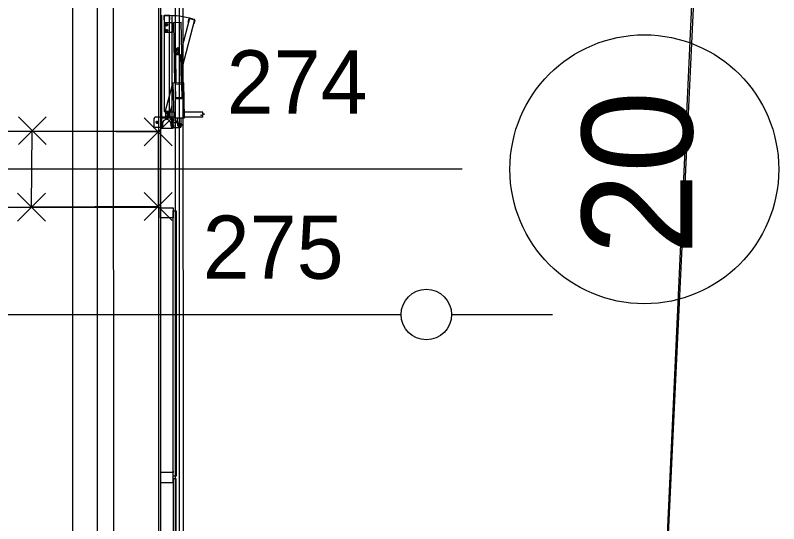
# Model space of a CAD drawing. Extents: x -264205 to -263659, y -1242401 to -1242060.
# Drawn here: x -263796.19 to -263790.15, y -1242212.69 to -1242208.66 of the extents above; entities that cross this region are included whole.
import ezdxf

# ---------------------------------------------------------------- set-up
doc = ezdxf.new("R2010")
doc.units = 0
for name, color, linetype in [('BOD_CISLO', 7, 'Continuous'), ('BOD_SYMBOL', 7, 'Continuous'), ('KFA_SO_10-1_BETONOVE_STLPY', 7, 'Continuous'), ('KFA_SO_10-1_PLACHTY', 7, 'Continuous'), ('KFA_SO_10-1_STRECHY', 7, 'Continuous'), ('KFA_SO_10-1_TRIBUNA_C_OBVOD', 7, 'Continuous'), ('OBRUBNIKY_KOMUNIKACIE_PROJEKT', 7, 'Continuous'), ('OSI_STAVBY_KFA', 7, 'Continuous'), ('SITUACIA_DSP_2D', 7, 'Continuous')]:
    doc.layers.add(name, color=color, linetype=linetype)

msp = doc.modelspace()

# ---------------------------------------------------------------- linework, layer by layer
at = {"layer": 'BOD_SYMBOL'}
for p, q in [((-263796.1675, -1242209.6875), (-263795.9465, -1242209.4665)), ((-263795.9465, -1242209.6875), (-263796.1675, -1242209.4665)), ((-263795.1705, -1242209.6965), (-263794.9495, -1242209.4755)), ((-263794.9495, -1242209.6965), (-263795.1705, -1242209.4755)), ((-263796.1735, -1242210.2935), (-263795.9525, -1242210.0725)), ((-263795.9525, -1242210.2935), (-263796.1735, -1242210.0725)), ((-263795.1715, -1242210.2885), (-263794.9505, -1242210.0675)), ((-263794.9505, -1242210.2885), (-263795.1715, -1242210.0675))]:
    msp.add_line(p, q, dxfattribs=at)
at = {"layer": 'KFA_SO_10-1_BETONOVE_STLPY'}
msp.add_lwpolyline([(-263795.06, -1242209.586), (-263795.061, -1242210.178), (-263796.063, -1242210.183), (-263796.057, -1242209.577)], close=True, dxfattribs=at)
at = {"layer": 'KFA_SO_10-1_PLACHTY'}
for p, q in [((-263794.856, -1242227.181), (-263794.865, -1242196.184)), ((-263790.262, -1242196.192), (-263791.751, -1242228.358))]:
    msp.add_line(p, q, dxfattribs=at)
for points in [[(-263795.396, -1242226.823), (-263795.427, -1242195.892), (-263795.456, -1242167.905), (-263795.427, -1242160.909), (-263795.402, -1242132.887), (-263795.428, -1242101.98)], [(-263794.927, -1242226.983), (-263794.921, -1242199.7), (-263794.865, -1242196.184)], [(-263791.76, -1242228.35), (-263790.229, -1242196.189)]]:
    msp.add_lwpolyline(points, dxfattribs=at)
at = {"layer": 'KFA_SO_10-1_STRECHY'}
msp.add_line((-263795.734, -1242227.196), (-263795.754, -1242101.588), dxfattribs=at)
at = {"layer": 'KFA_SO_10-1_TRIBUNA_C_OBVOD'}
msp.add_lwpolyline([(-263795.284, -1242101.267), (-263795.051, -1242101.819), (-263795.059, -1242226.991), (-263795.286, -1242227.548)], dxfattribs=at)
at = {"layer": 'OBRUBNIKY_KOMUNIKACIE_PROJEKT'}
msp.add_line((-263794.8928, -1242101.3822), (-263794.8928, -1242227.3822), dxfattribs=at)
at = {"layer": 'OSI_STAVBY_KFA'}
for p, q in [((-263795.5428, -1242083.2372), (-263795.5428, -1242246.7072)), ((-263792.6528, -1242209.8822), (-263909.3428, -1242209.8822)), ((-263792.6528, -1242209.8822), (-263792.6528, -1242209.8822))]:
    msp.add_line(p, q, dxfattribs=at)
msp.add_circle((-263791.2101, -1242209.8825), 1.0643, dxfattribs=at)
at = {"layer": 'SITUACIA_DSP_2D'}
for p, q in [((-263794.8928, -1242101.3822), (-263794.8928, -1242227.3822)), ((-263795.0428, -1242101.7691), (-263795.0428, -1242226.9954)), ((-263795.0327, -1242208.6624), (-263795.0327, -1242209.5569)), ((-263795.0147, -1242208.6694), (-263795.0147, -1242208.6994)), ((-263795.0127, -1242208.6674), (-263795.0127, -1242209.4259)), ((-263794.9727, -1242208.6674), (-263795.0127, -1242208.6674)), ((-263794.9747, -1242208.6654), (-263795.0107, -1242208.6654)), ((-263794.9757, -1242208.6692), (-263794.9667, -1242208.6692)), ((-263794.9727, -1242208.6674), (-263794.9727, -1242209.4259)), ((-263794.9707, -1242208.6694), (-263794.9707, -1242208.6994)), ((-263794.9527, -1242208.6624), (-263794.9527, -1242209.5569)), ((-263795.0127, -1242208.6994), (-263795.0147, -1242208.6994)), ((-263795.0067, -1242208.7249), (-263795.0067, -1242208.7999)), ((-263794.9527, -1242208.7249), (-263795.0067, -1242208.7249)), ((-263794.9927, -1242208.732), (-263794.9995, -1242208.736)), ((-263794.9859, -1242208.736), (-263794.9927, -1242208.732)), ((-263794.9698, -1242208.6845), (-263794.9727, -1242208.6845)), ((-263794.9707, -1242208.6994), (-263794.9727, -1242208.6994)), ((-263794.9467, -1242208.7249), (-263794.9527, -1242208.7249)), ((-263794.9467, -1242208.7249), (-263794.9467, -1242208.7999)), ((-263794.9394, -1242208.7202), (-263794.8784, -1242208.7189)), ((-263794.9394, -1242208.7202), (-263794.9298, -1242209.2011)), ((-263794.8688, -1242209.1999), (-263794.8784, -1242208.7189)), ((-263794.8111, -1242208.6885), (-263794.8742, -1242208.9316)), ((-263794.7725, -1242208.6989), (-263794.8713, -1242209.0755)), ((-263794.8213, -1242208.7189), (-263794.8136, -1242208.6899)), ((-263794.8194, -1242208.7194), (-263794.8213, -1242208.7189)), ((-263794.8111, -1242208.6885), (-263794.7725, -1242208.6989)), ((-263794.8087, -1242208.6871), (-263794.7739, -1242208.6964)), ((-263794.7788, -1242208.7303), (-263794.7807, -1242208.7298)), ((-263794.771, -1242208.7013), (-263794.7788, -1242208.7303)), ((-263794.9995, -1242208.736), (-263794.9995, -1242208.7438)), ((-263794.9995, -1242208.7438), (-263794.9927, -1242208.7478)), ((-263794.9927, -1242208.777), (-263794.9995, -1242208.781)), ((-263794.9995, -1242208.781), (-263794.9995, -1242208.7888)), ((-263794.9995, -1242208.7888), (-263794.9927, -1242208.7928)), ((-263794.9927, -1242208.7478), (-263794.9859, -1242208.7438)), ((-263794.9859, -1242208.781), (-263794.9927, -1242208.777)), ((-263794.9927, -1242208.7928), (-263794.9859, -1242208.7888)), ((-263794.9859, -1242208.7438), (-263794.9859, -1242208.736)), ((-263794.9859, -1242208.7888), (-263794.9859, -1242208.781)), ((-263794.9527, -1242208.7999), (-263795.0067, -1242208.7999)), ((-263794.9467, -1242208.7999), (-263794.9527, -1242208.7999)), ((-263794.9092, -1242208.9566), (-263794.9167, -1242208.9435)), ((-263794.8939, -1242208.9725), (-263794.9139, -1242208.9729)), ((-263794.9139, -1242208.9729), (-263794.9138, -1242208.9779)), ((-263794.9125, -1242208.9648), (-263794.9138, -1242208.9656)), ((-263794.9138, -1242208.9656), (-263794.9137, -1242208.9721)), ((-263794.9124, -1242208.9728), (-263794.9137, -1242208.9721)), ((-263794.8955, -1242208.9645), (-263794.9125, -1242208.9648)), ((-263794.8954, -1242208.9725), (-263794.9124, -1242208.9728)), ((-263794.9092, -1242208.9566), (-263794.8992, -1242208.9564)), ((-263794.9092, -1242208.9566), (-263794.909, -1242208.9648)), ((-263794.9089, -1242208.9655), (-263794.9088, -1242208.972)), ((-263794.8992, -1242208.9564), (-263794.8922, -1242208.943)), ((-263794.8992, -1242208.9564), (-263794.899, -1242208.9646)), ((-263794.8991, -1242208.9653), (-263794.899, -1242208.9718)), ((-263794.8955, -1242208.9645), (-263794.8942, -1242208.9652)), ((-263794.8954, -1242208.9725), (-263794.8941, -1242208.9717)), ((-263794.8942, -1242208.9652), (-263794.8941, -1242208.9717)), ((-263794.8939, -1242208.9725), (-263794.8938, -1242208.9775)), ((-263794.8838, -1242208.9773), (-263794.9238, -1242208.9781)), ((-263794.9238, -1242208.9781), (-263794.9193, -1242209.2009)), ((-263794.8838, -1242208.9773), (-263794.8793, -1242209.2001)), ((-263794.8558, -1242209.1996), (-263794.9428, -1242209.2013)), ((-263794.9428, -1242209.2013), (-263794.9373, -1242209.4763)), ((-263794.9243, -1242209.201), (-263794.9218, -1242209.327)), ((-263794.8741, -1242209.21), (-263794.9241, -1242209.211)), ((-263794.8743, -1242209.2), (-263794.8718, -1242209.326)), ((-263794.8504, -1242209.4745), (-263794.8558, -1242209.1996)), ((-263794.9527, -1242209.2248), (-263795.0055, -1242209.4216)), ((-263794.872, -1242209.316), (-263794.922, -1242209.317)), ((-263794.8718, -1242209.326), (-263794.9218, -1242209.327)), ((-263794.9527, -1242209.3794), (-263794.9668, -1242209.4319)), ((-263794.9727, -1242209.4259), (-263795.0127, -1242209.4259)), ((-263795.0055, -1242209.4216), (-263794.9668, -1242209.4319)), ((-263795.0052, -1242209.4259), (-263795.0052, -1242209.4359)), ((-263795.0052, -1242209.4259), (-263794.9802, -1242209.4259)), ((-263795.0052, -1242209.4359), (-263794.9802, -1242209.4359)), ((-263794.9982, -1242209.4235), (-263795.0008, -1242209.4332)), ((-263794.9767, -1242209.4397), (-263795.0008, -1242209.4332)), ((-263795.0008, -1242209.4455), (-263794.9937, -1242209.4359)), ((-263794.9937, -1242209.4669), (-263795.0008, -1242209.4573)), ((-263794.9897, -1242209.4362), (-263794.999, -1242209.4436)), ((-263794.9937, -1242209.4359), (-263794.9917, -1242209.4359)), ((-263794.9917, -1242209.4359), (-263794.9847, -1242209.4455)), ((-263794.9847, -1242209.4573), (-263794.9917, -1242209.4669)), ((-263794.9878, -1242209.4367), (-263794.9897, -1242209.4362)), ((-263794.9834, -1242209.4478), (-263794.9878, -1242209.4367)), ((-263794.9772, -1242209.4504), (-263794.9868, -1242209.4433)), ((-263794.9868, -1242209.4594), (-263794.9772, -1242209.4524)), ((-263794.9802, -1242209.4259), (-263794.9802, -1242209.4359)), ((-263794.9772, -1242209.4639), (-263794.9772, -1242209.4389)), ((-263794.9672, -1242209.4389), (-263794.9772, -1242209.4389)), ((-263794.9772, -1242209.4524), (-263794.9772, -1242209.4504)), ((-263794.9741, -1242209.43), (-263794.9767, -1242209.4397)), ((-263794.9672, -1242209.4314), (-263794.9672, -1242209.4714)), ((-263794.9382, -1242209.4314), (-263794.9672, -1242209.4314)), ((-263794.9672, -1242209.4639), (-263794.9672, -1242209.4389)), ((-263794.7071, -1242209.4314), (-263794.8512, -1242209.4314)), ((-263794.7221, -1242209.4554), (-263794.6921, -1242209.4474)), ((-263794.7071, -1242209.4594), (-263794.7221, -1242209.4554)), ((-263794.7071, -1242209.4434), (-263794.7071, -1242209.4314)), ((-263794.6921, -1242209.4474), (-263794.7071, -1242209.4434)), ((-263795.0927, -1242209.5569), (-263795.0927, -1242209.4809)), ((-263795.0327, -1242209.4709), (-263795.0827, -1242209.4709)), ((-263795.0547, -1242209.5109), (-263795.0807, -1242209.5109)), ((-263795.0677, -1242209.5239), (-263795.0677, -1242209.4979)), ((-263794.9527, -1242209.4709), (-263795.0327, -1242209.4709)), ((-263794.9527, -1242209.4769), (-263795.0327, -1242209.4769)), ((-263795.0052, -1242209.4669), (-263794.9802, -1242209.4669)), ((-263795.0052, -1242209.4769), (-263795.0052, -1242209.4669)), ((-263795.0052, -1242209.4769), (-263794.9802, -1242209.4769)), ((-263794.9917, -1242209.4669), (-263794.9937, -1242209.4669)), ((-263794.9802, -1242209.4769), (-263794.9802, -1242209.4669)), ((-263794.9672, -1242209.4639), (-263794.9772, -1242209.4639)), ((-263794.9374, -1242209.4714), (-263794.9672, -1242209.4714)), ((-263794.9375, -1242209.4709), (-263794.9527, -1242209.4709)), ((-263794.9527, -1242209.4819), (-263794.9427, -1242209.4819)), ((-263794.9527, -1242209.5519), (-263794.9527, -1242209.4819)), ((-263794.9329, -1242209.4924), (-263794.9472, -1242209.4924)), ((-263794.9427, -1242209.5519), (-263794.9427, -1242209.4819)), ((-263794.9427, -1242209.484), (-263794.9427, -1242209.5008)), ((-263794.941, -1242209.484), (-263794.9427, -1242209.484)), ((-263794.941, -1242209.5008), (-263794.9427, -1242209.5008)), ((-263794.9427, -1242209.5114), (-263794.9081, -1242209.5114)), ((-263794.941, -1242209.484), (-263794.941, -1242209.5008)), ((-263794.941, -1242209.4856), (-263794.941, -1242209.4992)), ((-263794.9355, -1242209.4856), (-263794.941, -1242209.4856)), ((-263794.941, -1242209.4924), (-263794.9364, -1242209.4924)), ((-263794.941, -1242209.4992), (-263794.9355, -1242209.4992)), ((-263794.9373, -1242209.4763), (-263794.8504, -1242209.4745)), ((-263794.9355, -1242209.4992), (-263794.9355, -1242209.4856)), ((-263794.9082, -1242209.5109), (-263794.9273, -1242209.5109)), ((-263794.9177, -1242209.5114), (-263794.9177, -1242209.5013)), ((-263794.9089, -1242209.4757), (-263794.9077, -1242209.5317)), ((-263794.8927, -1242209.547), (-263794.8927, -1242209.5158)), ((-263794.8777, -1242209.5311), (-263794.8789, -1242209.4751)), ((-263794.7071, -1242209.4714), (-263794.8504, -1242209.4714)), ((-263794.7071, -1242209.4714), (-263794.7071, -1242209.4594)), ((-263795.0327, -1242209.5509), (-263795.0927, -1242209.5509)), ((-263795.0427, -1242209.5569), (-263794.9427, -1242209.5569)), ((-263795.0252, -1242209.5409), (-263795.0327, -1242209.5409)), ((-263795.0252, -1242209.5199), (-263795.0252, -1242209.5409)), ((-263794.9602, -1242209.5199), (-263794.9602, -1242209.5409)), ((-263794.9527, -1242209.5409), (-263794.9602, -1242209.5409)), ((-263794.9527, -1242209.5519), (-263794.9427, -1242209.5519)), ((-263794.9329, -1242209.5414), (-263794.9472, -1242209.5414)), ((-263794.9427, -1242209.533), (-263794.9427, -1242209.5498)), ((-263794.941, -1242209.533), (-263794.9427, -1242209.533)), ((-263794.941, -1242209.5498), (-263794.9427, -1242209.5498)), ((-263794.9427, -1242209.5514), (-263794.8927, -1242209.5514)), ((-263794.941, -1242209.533), (-263794.941, -1242209.5498)), ((-263794.941, -1242209.5346), (-263794.941, -1242209.5482)), ((-263794.9355, -1242209.5346), (-263794.941, -1242209.5346)), ((-263794.941, -1242209.5414), (-263794.9364, -1242209.5414)), ((-263794.941, -1242209.5482), (-263794.9355, -1242209.5482)), ((-263794.9355, -1242209.5482), (-263794.9355, -1242209.5346)), ((-263794.8771, -1242209.5314), (-263794.9083, -1242209.5314)), ((-263794.9045, -1242209.5314), (-263794.8986, -1242209.5212)), ((-263794.8986, -1242209.5416), (-263794.9045, -1242209.5314)), ((-263794.8986, -1242209.5212), (-263794.8869, -1242209.5212)), ((-263794.8869, -1242209.5416), (-263794.8986, -1242209.5416)), ((-263794.8869, -1242209.5212), (-263794.881, -1242209.5314)), ((-263794.881, -1242209.5314), (-263794.8869, -1242209.5416)), ((-263795.0378, -1242209.5823), (-263796.5378, -1242209.5823)), ((-263795.0378, -1242210.1823), (-263795.0378, -1242209.5823)), ((-263796.5378, -1242210.1823), (-263795.0378, -1242210.1823)), ((-263795.0427, -1242210.2673), (-263795.0427, -1242210.1873)), ((-263795.0427, -1242210.1873), (-263794.9427, -1242210.1873)), ((-263794.9427, -1242210.1873), (-263794.9427, -1242210.2273)), ((-263794.9427, -1242212.3123), (-263794.9427, -1242210.2123)), ((-263794.9427, -1242210.2123), (-263794.9177, -1242210.2123)), ((-263794.9427, -1242210.2273), (-263794.9427, -1242210.2673)), ((-263794.9177, -1242210.2123), (-263794.9177, -1242212.3123)), ((-263794.9427, -1242210.2673), (-263795.0427, -1242210.2673)), ((-263800.5928, -1242211.0322), (-263793.1362, -1242211.0322)), ((-263792.7362, -1242211.0322), (-263791.9362, -1242211.0322)), ((-263794.9427, -1242212.2823), (-263795.0427, -1242212.2823)), ((-263795.0427, -1242212.2823), (-263795.0427, -1242212.3623)), ((-263794.9427, -1242212.2723), (-263794.9427, -1242212.2823)), ((-263794.9427, -1242212.3623), (-263794.9427, -1242212.2723)), ((-263794.9177, -1242212.3123), (-263794.9427, -1242212.3123)), ((-263794.9177, -1242212.3323), (-263794.9427, -1242212.3323)), ((-263794.9427, -1242212.3323), (-263794.9427, -1242214.4323)), ((-263794.9177, -1242214.4323), (-263794.9177, -1242212.3323)), ((-263795.0427, -1242212.3623), (-263794.9427, -1242212.3623))]:
    msp.add_line(p, q, dxfattribs=at)
for centre, radius in [((-263794.9927, -1242208.7399), 0.0084), ((-263794.9927, -1242208.7399), 0.0068), ((-263794.9927, -1242208.7849), 0.0084), ((-263794.9927, -1242208.7849), 0.0068), ((-263794.9046, -1242208.9365), 0.00952), ((-263794.9046, -1242208.9365), 0.00645), ((-263794.9046, -1242208.9365), 0.005), ((-263795.0677, -1242209.5109), 0.008), ((-263794.8927, -1242209.5314), 0.0126), ((-263794.8927, -1242209.5314), 0.0102), ((-263792.9362, -1242211.0322), 0.2)]:
    msp.add_circle(centre, radius, dxfattribs=at)
for centre, radius, start, end in [((-263795.0107, -1242208.6694), 0.004, 90, 180), ((-263794.9927, -1242209.4514), 0.7862, 74.99999, 90), ((-263794.9747, -1242208.6694), 0.004, 0, 90), ((-263794.8097, -1242208.691), 0.004, 74.99999, 165), ((-263794.7749, -1242208.7003), 0.004, 345, 74.99999), ((-263794.9046, -1242208.9365), 0.014, 332.4029, 209.8771), ((-263794.9113, -1242208.9691), 0.00432, 56.54657, 125.73344), ((-263794.9113, -1242208.9685), 0.00432, 236.54657, 305.73344), ((-263794.9037, -1242208.9808), 0.0161, 73.44008, 108.83992), ((-263794.9042, -1242208.9565), 0.0161, 253.44008, 288.83992), ((-263794.8991, -1242208.9653), 0.0001, 181.14001, 250.32684), ((-263794.8966, -1242208.9688), 0.00432, 56.54657, 125.73344), ((-263794.899, -1242208.9718), 0.0001, 111.95316, 181.14001), ((-263794.8966, -1242208.9682), 0.00432, 236.54657, 305.73344), ((-263794.9927, -1242209.4514), 0.01, 323.61393, 216.38607), ((-263794.9927, -1242209.4514), 0.01, 53.61392, 306.38608), ((-263794.9927, -1242209.4514), 0.01, 128.61393, 21.38609), ((-263794.9927, -1242209.4514), 0.01, 143.61393, 36.38607), ((-263795.0827, -1242209.4809), 0.01, 90, 180), ((-263794.9927, -1242209.5199), 0.0325, 0, 180), ((-263794.9423, -1242209.489), 0.0068, 330, 30), ((-263794.9423, -1242209.4958), 0.0068, 330, 30), ((-263794.9177, -1242209.5109), 0.008, 356.41668, 183.58332), ((-263794.8927, -1242209.5314), 0.02, 270, 42.54962), ((-263794.9423, -1242209.538), 0.0068, 330, 30), ((-263794.9423, -1242209.5448), 0.0068, 330, 30), ((-263794.8927, -1242209.5314), 0.015, 181.14001, 1.14001)]:
    msp.add_arc(centre, radius, start, end, dxfattribs=at)

# ---------------------------------------------------------------- texts
at = {"layer": 'BOD_CISLO'}
for s, p in [('274', (-263794.5173, -1242209.4412)), ('275', (-263794.7074, -1242210.7488))]:
    msp.add_text(s, height=0.5, dxfattribs=at).set_placement(p)
at = {"layer": 'OSI_STAVBY_KFA'}
msp.add_text('20', height=0.875, rotation=90, dxfattribs=at).set_placement((-263790.8295, -1242210.5623))

doc.saveas('drawing.dxf')
